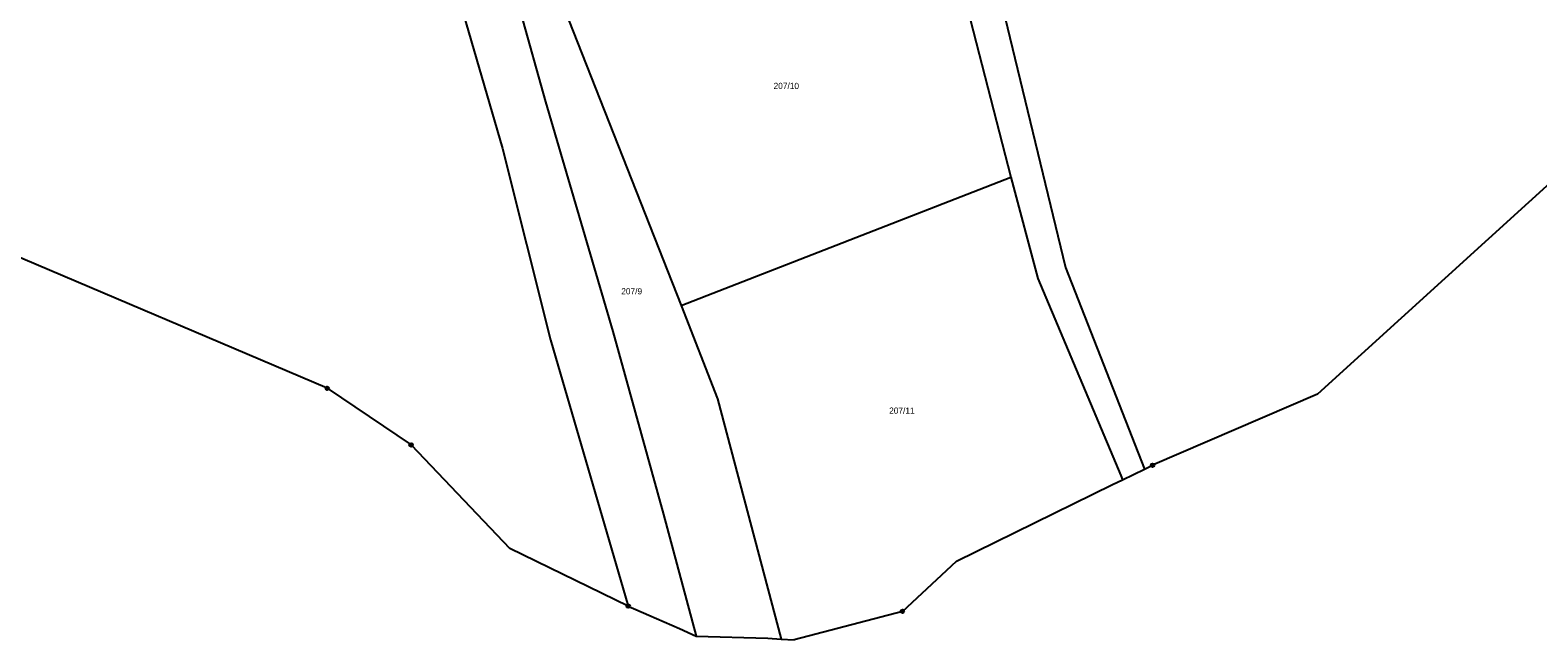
# Model space of a CAD drawing. Extents: x -633485 to -630509, y -1112692 to -1108818.
# Drawn here: x -631981.6 to -631569.8, y -1112413.1 to -1112246.7 of the extents above; entities that cross this region are included whole.
import ezdxf

# ---------------------------------------------------------------- set-up
doc = ezdxf.new("R2010")
doc.units = 0
doc.header["$LTSCALE"] = 0.68
doc.layers.add('1', color=7, linetype='Continuous', lineweight=25)
doc.layers.add('8', color=7, linetype='Continuous', lineweight=25)
doc.layers.add('2', color=7, linetype='Continuous')

msp = doc.modelspace()

# ---------------------------------------------------------------- linework, layer by layer
at = {"layer": '1'}
for p, q in [((-631871.65, -1112213.51), (-631852.59, -1112278.99)), ((-631719.65, -1112225.54), (-631698.79, -1112311.55)), ((-631837.04, -1112237.53), (-631803.82, -1112321.88)), ((-631847.63, -1112241.93), (-631840.88, -1112266.32)), ((-631725.61, -1112240.9), (-631713.72, -1112286.84)), ((-631840.88, -1112266.32), (-631822.45, -1112328.96)), ((-631852.59, -1112278.99), (-631839.44, -1112331.27)), ((-631553.28, -1112276.42), (-631629.96, -1112346.06)), ((-631900.43, -1112344.49), (-632038.44, -1112285.9)), ((-631803.82, -1112321.88), (-631713.72, -1112286.84)), ((-631713.72, -1112286.84), (-631706.38, -1112314.52)), ((-631698.79, -1112311.55), (-631677.2, -1112366.55)), ((-631706.38, -1112314.52), (-631683.66, -1112368.25)), ((-631803.82, -1112321.88), (-631793.89, -1112347.32)), ((-631839.44, -1112331.27), (-631818.25, -1112403.92)), ((-631822.45, -1112328.96), (-631808.6, -1112378.95)), ((-631900.43, -1112344.49), (-631877.53, -1112359.95)), ((-631793.89, -1112347.32), (-631776.51, -1112412.94)), ((-631629.96, -1112346.06), (-631675.02, -1112365.5)), ((-631877.53, -1112359.95), (-631850.54, -1112388.21)), ((-631686.01, -1112370.77), (-631683.22, -1112369.43)), ((-631683.66, -1112368.25), (-631683.22, -1112369.43)), ((-631683.22, -1112369.43), (-631677.2, -1112366.55)), ((-631677.2, -1112366.55), (-631675.02, -1112365.5)), ((-631728.58, -1112391.66), (-631686.01, -1112370.77)), ((-631808.6, -1112378.95), (-631799.68, -1112412.1)), ((-631818.25, -1112403.92), (-631850.54, -1112388.21)), ((-631743.37, -1112405.37), (-631728.58, -1112391.66)), ((-631818.25, -1112403.92), (-631812.62, -1112406.4)), ((-631812.62, -1112406.4), (-631804.26, -1112410.08)), ((-631743.37, -1112405.37), (-631772.9, -1112413.14)), ((-631804.26, -1112410.08), (-631799.68, -1112412.1)), ((-631799.68, -1112412.1), (-631780.14, -1112412.73)), ((-631780.14, -1112412.73), (-631776.51, -1112412.94)), ((-631776.51, -1112412.94), (-631772.9, -1112413.14))]:
    msp.add_line(p, q, dxfattribs=at)
at = {"layer": '8'}
for centre, radius in [((-631900.43, -1112344.4899), 0.5), ((-631900.43, -1112344.4899), 0.0303), ((-631877.53, -1112359.9499), 0.5), ((-631877.53, -1112359.9499), 0.0303), ((-631675.02, -1112365.4999), 0.5), ((-631675.02, -1112365.4999), 0.0303), ((-631818.25, -1112403.9199), 0.5), ((-631818.25, -1112403.9199), 0.0303), ((-631743.37, -1112405.3699), 0.5), ((-631743.37, -1112405.3699), 0.0303)]:
    msp.add_circle(centre, radius, dxfattribs=at)

# ---------------------------------------------------------------- texts
at = {"layer": '2'}
for s, p in [('207/10', (-631778.55, -1112262.805)), ('207/9', (-631820.15, -1112318.855)), ('207/11', (-631746.98, -1112351.435))]:
    msp.add_text(s, height=1.7, dxfattribs=at).set_placement(p)

doc.saveas('drawing.dxf')
